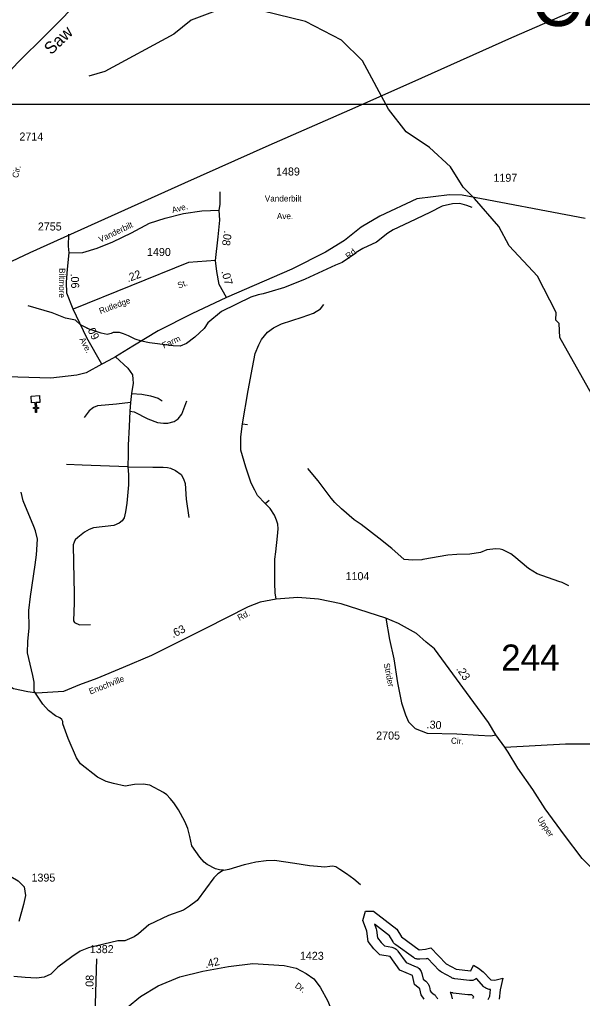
# Model space of a CAD drawing. Extents: x 1473865 to 1648260, y 639067 to 773536.
# Drawn here: x 1505359 to 1509749, y 649038 to 656681 of the extents above; entities that cross this region are included whole.
import ezdxf

# ---------------------------------------------------------------- set-up
doc = ezdxf.new("R2010")
doc.units = 0
for name, color, linetype in [('Exist Cultural Church CELL', 7, 'Continuous'), ('Exist Hydrographic Buffer Line', 7, 'Continuous'), ('Exist Hydrographic Creek Single Shore', 7, 'Continuous'), ('Exist Hydrographic Lake Shore', 7, 'Continuous'), ('Exist Hydrographic Misc Water Feature', 7, 'Continuous'), ('Exist Road Non-System Type 51', 7, 'Continuous'), ('Exist Road Non-System Type 51 Label', 7, 'Continuous'), ('Exist Road Secondary Mileage Hundredths English Label', 7, 'Continuous'), ('Exist Road Secondary Structure Culvert Number Label', 7, 'Continuous'), ('Exist Road Secondary Structure Standard Bridge Number Label', 7, 'Continuous'), ('Exist Road Secondary Type 51 Attributed', 7, 'Continuous'), ('Exist Road Secondary Type 51 Label', 7, 'Continuous'), ('Exist Road Secondary Type 51 Number Label', 7, 'Continuous'), ('Exist Utilities Electrical Transmission Line', 7, 'Continuous'), ('Map Preparation Inset Cut Line', 7, 'Continuous')]:
    doc.layers.add(name, color=color, linetype=linetype)

msp = doc.modelspace()

# ---------------------------------------------------------------- linework, layer by layer
at = {"layer": 'Exist Cultural Church CELL'}
msp.add_lwpolyline([(1505516.8, 653691.9), (1505488.4, 653690.4), (1505490.4, 653652.3), (1505506.3, 653653.2), (1505506.7, 653645.2), (1505490.8, 653644.4), (1505492.3, 653614.3), (1505484.3, 653613.9), (1505482.8, 653644), (1505466.8, 653643.1), (1505466.4, 653651.1), (1505482.3, 653651.9), (1505480.4, 653690), (1505451.6, 653688.5), (1505448.8, 653741.7), (1505514, 653745.1)], close=True, dxfattribs=at)
at = {"layer": 'Exist Hydrographic Buffer Line'}
for points in [[(1509013, 649028.5), (1509027.3, 649055), (1509033.2, 649107.1), (1509029, 649107.4), (1509021.8, 649108.2), (1509014.8, 649109.8), (1509007.9, 649111.9), (1509001.3, 649114.8), (1508995, 649118.3), (1508989, 649122.3), (1508983.4, 649126.9), (1508978.4, 649132.1), (1508925.4, 649190.9), (1508923.6, 649192.3), (1508915.6, 649186.9), (1508904.9, 649181.9), (1508893.5, 649178.6), (1508881.7, 649177.2), (1508869.9, 649177.7), (1508754.9, 649191.2), (1508747.7, 649192.4), (1508740.5, 649194.3), (1508733.7, 649196.9), (1508727.1, 649200.2), (1508650.4, 649243.1), (1508641.2, 649249.2), (1508633, 649256.5), (1508544.1, 649348.9), (1508543.9, 649348.8), (1508536.7, 649347.3), (1508529.5, 649346.5), (1508480.5, 649343.4), (1508474.1, 649343.3), (1508467.7, 649343.7), (1508461.3, 649344.7), (1508455.1, 649346.2), (1508449, 649348.2), (1508443.1, 649350.8), (1508437.4, 649353.8), (1508432.1, 649357.3), (1508293.3, 649456.9), (1508287.3, 649461.6), (1508281.9, 649467), (1508277, 649472.9), (1508272.7, 649479.2), (1508243.7, 649527.6), (1508128, 649618.3), (1508138.8, 649589.4), (1508141.5, 649580.5), (1508143.1, 649571.3), (1508149.8, 649511.2), (1508179, 649474.2), (1508204.7, 649448.5), (1508263.2, 649437.7), (1508270.2, 649436.1), (1508277, 649433.7), (1508283.6, 649430.8), (1508289.8, 649427.2), (1508295.7, 649423.1), (1508301.2, 649418.4), (1508306.1, 649413.2), (1508310.6, 649407.5), (1508373.7, 649319.2), (1508453.8, 649285.2), (1508461.8, 649281.2), (1508469.3, 649276.3), (1508476.2, 649270.5), (1508482.3, 649264), (1508487.6, 649256.8), (1508492, 649249), (1508495.4, 649240.7), (1508497.8, 649232.1), (1508507.2, 649189.1), (1508528.2, 649172.6), (1508533.3, 649168.2), (1508538, 649163.3), (1508542.2, 649158.1), (1508546, 649152.5), (1508549.2, 649146.6), (1508551.9, 649140.4), (1508554, 649134), (1508555.5, 649127.4), (1508561.5, 649095.8), (1508568.7, 649085.8), (1508592.3, 649068.7), (1508597.1, 649064.8), (1508601.6, 649060.6), (1508605.8, 649056.1), (1508609.5, 649051.2), (1508612.9, 649046), (1508615.8, 649040.5), (1508618.2, 649034.8)], [(1508897.3, 649036.9), (1508898.5, 649041.5), (1508900.3, 649047.7), (1508901.3, 649050.8), (1508898.8, 649053.3), (1508896.9, 649055.2), (1508895.1, 649057.2), (1508887.7, 649065.4), (1508886.3, 649065.3), (1508877.4, 649065.3), (1508865.6, 649065.7), (1508861.2, 649066), (1508856.8, 649066.4), (1508741.8, 649080), (1508739.1, 649080.3), (1508736.4, 649080.7), (1508729.1, 649082), (1508723.7, 649083), (1508718.9, 649084.2), (1508721.1, 649079.2), (1508722.8, 649074.9), (1508724.4, 649070.6), (1508726.4, 649064.7), (1508727.7, 649060.3), (1508728.9, 649055.9), (1508730.4, 649049.9), (1508731.4, 649045.4), (1508732.3, 649040.8), (1508733.2, 649034.7)]]:
    msp.add_lwpolyline(points, dxfattribs=at)
at = {"layer": 'Exist Hydrographic Creek Single Shore'}
for points in [[(1508908.8, 655285.2), (1508818.8, 655372.4), (1508720.8, 655531.9), (1508556.8, 655682.9), (1508375.8, 655804.7), (1508236.8, 655981.6), (1508034.8, 656359.8), (1507870.8, 656520.7), (1507589.8, 656667.5), (1507141.8, 656775), (1506966.8, 656778.5), (1506697.8, 656675.6), (1506562.8, 656566.7), (1506023.8, 656275.6), (1505898.8, 656238.8)], [(1510180, 652516.1), (1510180, 652579.4), (1510146.9, 652645.8), (1510074.5, 652778.5), (1510026.2, 652862.9), (1510065.4, 652935.3), (1510026.2, 653001.7), (1509993, 653101.2), (1509937.8, 653551), (1509573.8, 654198.4), (1509567.8, 654306.9), (1509542.8, 654333.7), (1509543.8, 654392.7), (1509398.7, 654677.9), (1509177.8, 654915.5), (1509096.8, 655064.8), (1508908.8, 655285.2)]]:
    msp.add_lwpolyline(points, dxfattribs=at)
at = {"layer": 'Exist Hydrographic Lake Shore'}
msp.add_lwpolyline([(1508515, 649032.2), (1508490.9, 649065.3), (1508481.8, 649113.6), (1508439.6, 649146.8), (1508424.5, 649216.2), (1508325, 649258.4), (1508249.6, 649364), (1508168.1, 649379), (1508122.9, 649424.3), (1508077.6, 649481.6), (1508068.6, 649563), (1508050.5, 649611.3), (1508035.4, 649647.5), (1508058.2, 649719.1), (1508119.9, 649719.9), (1508300.8, 649578.1), (1508337, 649517.8), (1508475.8, 649418.3), (1508524.8, 649421.3), (1508567.6, 649432.6), (1508687.1, 649308.5), (1508763.7, 649265.7), (1508878.6, 649252.1), (1508898.9, 649297.3), (1508939.7, 649274.4), (1508976.5, 649246.3), (1509034.1, 649182.2), (1509067, 649180), (1509129.7, 649195.1), (1509108.5, 649105.5), (1509100.2, 649032.2)], dxfattribs=at)
at = {"layer": 'Exist Hydrographic Misc Water Feature'}
for points in [[(1508890.4, 655213.1), (1508847.7, 655229.4), (1508792, 655244.4), (1508735.9, 655241.5), (1508655.6, 655225), (1508558.7, 655174.8), (1508400.5, 655099.4), (1508272.4, 655040.3), (1508231.9, 655013.1), (1508142.6, 654942.8), (1508037.8, 654894.8), (1507985.2, 654863.8), (1507981.1, 654857.9), (1507875.8, 654783.9), (1507823.4, 654762.9), (1507585.6, 654653.5), (1507426.2, 654590.1), (1507303.7, 654552.9), (1507259.5, 654539.7), (1507219.4, 654532.5), (1507163.1, 654513.5), (1506933.1, 654401.9), (1506827.5, 654313.6), (1506798.7, 654268.6), (1506725.5, 654202), (1506660.6, 654151.2), (1506612.3, 654132.1), (1506556.3, 654133.2), (1506516.4, 654137.9), (1506372.8, 654156.6), (1506309, 654169.8), (1506261.3, 654186.7), (1506209.8, 654211.6), (1506170.1, 654228.4), (1506138.3, 654237), (1506090.3, 654237.9), (1506074.1, 654230.2), (1506042, 654222.8), (1505994.2, 654231.7), (1505901.2, 654264.4), (1505835.4, 654298.6), (1505796.1, 654335.3), (1505718.4, 654348.8), (1505613.2, 654390.8), (1505426.2, 654446.2)], [(1509642.5, 652258.7), (1509633.9, 652264.5), (1509590.4, 652285.3), (1509566.5, 652293.7), (1509397.6, 652352.2), (1509328.3, 652394.2), (1509214.2, 652492.2), (1509190.4, 652508.7), (1509129, 652539.8), (1509107.2, 652546.2), (1509075.2, 652548.8), (1509003.1, 652540.2), (1508954.7, 652521.1), (1508870.4, 652506.7), (1508770.5, 652504.6), (1508698.4, 652497.9), (1508505.8, 652465.6), (1508497.7, 652461.7), (1508425.7, 652459.1), (1508357.8, 652464.3), (1508263.4, 652550.1), (1508160.8, 652632), (1508022.8, 652738.5), (1507967.8, 652776.1), (1507870.9, 652859.7), (1507818, 652910.2), (1507790.6, 652944.7), (1507687.1, 653080.6), (1507606.8, 653176)], [(1506949.7, 650038.7), (1506918.3, 650041), (1506886.4, 650049.6), (1506823.1, 650082.8), (1506799.4, 650101.2), (1506764.1, 650141.8), (1506701.7, 650228.9), (1506687, 650301.2), (1506672.2, 650365.4), (1506649.2, 650419.8), (1506598.9, 650510.7), (1506561.8, 650565.4), (1506534.5, 650597.9), (1506507, 650626.4), (1506481.4, 650646.8), (1506374.3, 650702.8), (1506323.9, 650709.7), (1506254.5, 650709.1), (1506182.3, 650694.4), (1506090.6, 650716.1), (1506035, 650731.1), (1505967.6, 650766.4), (1505833.5, 650868.8), (1505802.3, 650917.4), (1505737, 651066.6), (1505695.2, 651183.2), (1505695.5, 651199.2), (1505687.8, 651215.4), (1505672, 651229.7), (1505640.3, 651244.2), (1505585.1, 651285.2), (1505540, 651336.1), (1505473.3, 651435.9), (1505473.1, 651507.2), (1505462, 651559.4), (1505421.2, 651736.1), (1505422.8, 651824), (1505432.7, 651931.7), (1505431.2, 652067.7), (1505445.1, 652175.3), (1505481.6, 652422.5), (1505491.1, 652502.2), (1505498.4, 652623.9), (1505482.5, 652690.3), (1505471.1, 652722.5), (1505386.7, 652923.9), (1505371.9, 652992.2)], [(1506949.7, 650038.7), (1506994.4, 650047.6), (1507113, 650083.3), (1507201.4, 650105.6), (1507283.6, 650116.1), (1507347.6, 650116.9), (1507507.1, 650093.9)], [(1507507.1, 650093.9), (1507621.3, 650076.2), (1507683.4, 650069.7), (1507740.2, 650065.9), (1507779.1, 650070.3), (1507799.8, 650072.4), (1507825.6, 650066.7), (1507856.2, 650047.9), (1507910, 650013.2), (1507966, 649970.6), (1508018.3, 649928.1)], [(1506949.7, 650038.7), (1506905.7, 650011.3), (1506873.2, 649979.9), (1506744, 649802.4), (1506685.2, 649757.6), (1506636.7, 649726.5), (1506519.9, 649684.7), (1506366.6, 649611.6), (1506285.4, 649541.2), (1506252.9, 649517.9), (1506180.4, 649487.2), (1506124.5, 649488.3), (1505895.5, 649432.6), (1505831, 649405.8), (1505766.2, 649363.1), (1505656.8, 649281.2), (1505603.8, 649226.2), (1505551.5, 649203.3), (1505491.3, 649196.4), (1505403.4, 649200), (1505315.5, 649209.7)]]:
    msp.add_lwpolyline(points, dxfattribs=at)
at = {"layer": 'Exist Road Non-System Type 51'}
for p, q in [((1506233.1, 653762.6), (1506224.8, 653692.4)), ((1506224.8, 653692.4), (1506218, 653624.6)), ((1507098.8, 653525.8), (1507137.3, 653519.8)), ((1507274.5, 652903.7), (1507305.4, 652928.5))]:
    msp.add_line(p, q, dxfattribs=at)
for points in [[(1505746.1, 654859), (1505853.6, 654863.7), (1505963.1, 654895.4), (1506087.5, 654946), (1506233.3, 655015), (1506372.9, 655091.2), (1506495.5, 655129.5), (1506638.3, 655167.8), (1506781.8, 655186.8), (1506916, 655193.4)], [(1505746.1, 654859), (1505741.7, 654911), (1505742, 655004.6)], [(1505733.5, 654733.2), (1505746.1, 654859)], [(1507098.8, 653525.8), (1507143.3, 653783.7), (1507176.5, 653965.4), (1507196.9, 654073.3), (1507225.5, 654141.9), (1507247.4, 654183.4), (1507293.4, 654239.2), (1507340.9, 654274.6), (1507401.2, 654305.5), (1507563.3, 654357.6), (1507651.6, 654389.2), (1507707.4, 654423.9), (1507732.3, 654455.6)], [(1506107.6, 654047.6), (1506203.7, 653958.6), (1506239.9, 653907.4), (1506242.9, 653874.2), (1506245.2, 653843.3), (1506233.1, 653762.6)], [(1506233.1, 653762.6), (1506313.8, 653757.3), (1506380.2, 653742.2), (1506440.5, 653724.1), (1506471.4, 653703)], [(1506224.8, 653692.4), (1506114.7, 653678.1), (1505966.9, 653664.5), (1505936, 653653.2), (1505900.6, 653626.1), (1505863.6, 653573.3)], [(1506218, 653624.6), (1506253.5, 653617.8), (1506360.6, 653564.2), (1506433.7, 653534.8), (1506481.2, 653528.8), (1506514.4, 653528.8), (1506564.2, 653541.6), (1506595.1, 653563.5), (1506626, 653598.9), (1506663.7, 653704.5)], [(1506218, 653624.6), (1506214.3, 653503.9), (1506205.2, 653356.9), (1506205.2, 653286.7), (1506203.7, 653188.7)], [(1507274.5, 652903.7), (1507214.2, 652966.3), (1507193.8, 653005.5), (1507164.4, 653062), (1507123, 653185.7), (1507086, 653319.2), (1507083.7, 653362.9), (1507083.7, 653422.5), (1507098.8, 653525.8)], [(1506203.7, 653188.7), (1505846.3, 653202.3), (1505724.1, 653206.8)], [(1506203.7, 653188.7), (1506209.8, 653129.1), (1506209.8, 653049.2), (1506196.9, 652905.9), (1506184.9, 652837.3), (1506173.6, 652789.8), (1506160, 652767.2), (1506135.1, 652748.3), (1506095.1, 652729.5), (1505936.8, 652712.1), (1505901.3, 652700.8), (1505864.4, 652678.9), (1505812.3, 652637.5), (1505792, 652618.6), (1505783.7, 652599.8), (1505776.9, 652579.4), (1505779.2, 652442.2), (1505785.2, 652197.1), (1505785.2, 652126.9), (1505779.9, 651985.9), (1505787.5, 651973.9), (1505825.9, 651955), (1505911.9, 651956.5)], [(1506203.7, 653188.7), (1506399, 653187.2), (1506478.2, 653187.2), (1506513.7, 653182.7), (1506536.3, 653177.4), (1506574.7, 653160.8), (1506618.5, 653129.9), (1506638.8, 653094.4), (1506650.9, 653059), (1506659.2, 652936.8), (1506678.8, 652792.1)], [(1507359.7, 652156.4), (1507352.2, 652206.1), (1507349.9, 652280), (1507351.4, 652404.5), (1507351.4, 652467), (1507359, 652525.1), (1507371.1, 652647.3), (1507376.3, 652705.3), (1507372.6, 652740), (1507364.3, 652773.2), (1507347.7, 652810.9), (1507314.5, 652862.2), (1507274.5, 652903.7)], [(1509143.5, 650999.1), (1509616.5, 651025.3), (1510035.8, 651025.3), (1510345.2, 651016.6)]]:
    msp.add_lwpolyline(points, dxfattribs=at)
at = {"layer": 'Exist Road Secondary Type 51 Attributed'}
for points in [[(1505158.5, 656145.5), (1505346.5, 656347.2), (1505567.3, 656564.8), (1505873.4, 656877.7), (1506053.7, 657064), (1506308.5, 657324.9), (1506447.3, 657478), (1506532.1, 657592.5), (1506701.7, 657864.1), (1506751.5, 657960.8), (1506777.9, 658039.9)], [(1506887, 654799.4), (1506909.1, 654983.6), (1506920.2, 655116.3), (1506916, 655193.4), (1506923.8, 655237.9), (1506923.8, 655337.4)], [(1509771.7, 655126.8), (1508811.6, 655310.6), (1508711.9, 655313.8), (1508457.7, 655280.4), (1508170.3, 655145.7), (1508022.4, 655059.2), (1507892.9, 654955.4), (1507745.4, 654865.7), (1507482.7, 654733), (1506973.3, 654511.3)], [(1506887, 654799.4), (1506677.1, 654784.6), (1505777.6, 654419.8)], [(1506973.3, 654511.3), (1506917.1, 654612.4), (1506897.9, 654714.1), (1506887, 654799.4)], [(1505777.6, 654419.8), (1505726.6, 654545.8), (1505723.9, 654631.8), (1505733.5, 654733.2)], [(1506973.3, 654511.3), (1506703, 654383.8), (1506439.9, 654250.3), (1506243, 654131.5), (1506107.6, 654047.6), (1506054.5, 654019.6), (1506000.3, 653989.8)], [(1506000.3, 653989.8), (1505884.9, 654196.6), (1505777.6, 654419.8)], [(1506000.3, 653989.8), (1505877.2, 653922.8), (1505804.8, 653903.4), (1505603.6, 653881.8), (1504996.5, 653898.9), (1504811.6, 653896.1), (1504735.8, 653888.7), (1504655.4, 653871.1), (1504576.9, 653837.8), (1504492.8, 653807.3)], [(1508215.5, 652006.8), (1507866.8, 652118.1), (1507691.5, 652154.8), (1507529.7, 652169.5), (1507359.7, 652156.4), (1507236.8, 652131.5), (1507141.8, 652095.3), (1506808.2, 651926.6), (1506387.7, 651716), (1506168.1, 651621.8), (1505962.9, 651536.8), (1505826.2, 651486.9), (1505702.2, 651435.7), (1505576.5, 651426.1), (1505493.3, 651422.4), (1505423.4, 651431.6), (1505312.8, 651456.3), (1505173.1, 651544.8)], [(1509075.3, 651097.1), (1509016.5, 651192.2), (1508595.9, 651766.7), (1508531.1, 651820.8), (1508455.4, 651887.8), (1508314.9, 651965.7), (1508215.5, 652006.8)], [(1508215.5, 652006.8), (1508244.6, 651840.3), (1508278.2, 651689.8), (1508307.2, 651503.3), (1508337.4, 651347.2), (1508368.2, 651251.7)], [(1508368.2, 651251.7), (1508392.6, 651196.5), (1508444.5, 651146.7), (1508539.6, 651109.9), (1508768.7, 651103.4), (1508937.8, 651093.3), (1509034.8, 651087.8), (1509075.3, 651097.1)], [(1510974.3, 649458.1), (1510706, 649547.5), (1510476.6, 649621.9), (1510372.4, 649661.8), (1510170.8, 649767), (1510037.4, 649858.5), (1509866.7, 650010.4), (1509748.5, 650130.4), (1509609.7, 650312.2), (1509458.8, 650518.6), (1509362.3, 650669.1), (1509246.6, 650834.9), (1509170.9, 650961.6), (1509143.5, 650999.1), (1509075.3, 651097.1)], [(1505032.6, 650151), (1505290.8, 649989.3), (1505347.8, 649955.1), (1505364.9, 649940.8), (1505395.9, 649910.5), (1505404.4, 649842), (1505390.2, 649770.6), (1505353.1, 649639.4)], [(1505951.5, 648924.6), (1505950.5, 648994.7), (1505962.2, 649346.8)], [(1506137.7, 648941.7), (1506202.1, 648970.8), (1506303.4, 649053.2), (1506440.8, 649135.1), (1506609.9, 649206.3), (1506788.4, 649249.5), (1506989.1, 649288.3), (1507177.4, 649309.3), (1507423.1, 649295.6), (1507516.9, 649274.1), (1507594.1, 649232.9), (1507655.5, 649189.8), (1507704.6, 649125), (1507764.8, 649016.1), (1507807, 648905.4), (1507841.2, 648786.9), (1507867.6, 648678.5)]]:
    msp.add_lwpolyline(points, dxfattribs=at)
at = {"layer": 'Exist Utilities Electrical Transmission Line'}
msp.add_lwpolyline([(1509710.8, 656762.3), (1509197, 656538.7), (1508494, 656224.3), (1507974.2, 655991.1), (1507303.4, 655698.1), (1506646.5, 655403), (1505969.6, 655098.2), (1505439.7, 654859), (1504964, 654634.9), (1504530.8, 654436.1), (1504168, 654270.1), (1503557.6, 653996.3), (1503342.2, 653899.8), (1503190.9, 653832.2), (1502578.4, 653670.4)], dxfattribs=at)
at = {"layer": 'Map Preparation Inset Cut Line'}
msp.add_lwpolyline([(1500603.9, 656021.6), (1510544.7, 656021.6), (1510544.7, 642848.3), (1500603.9, 642848.3)], close=True, dxfattribs=at)

# ---------------------------------------------------------------- texts
at = {"layer": 'Exist Road Non-System Type 51 Label'}
for s, rotation, p in [('Ave.', 15.00826, (1506553.3, 655169.8)), ('Vanderbilt', 25.33225, (1505989.2, 654940))]:
    msp.add_text(s, height=47.5, rotation=rotation, dxfattribs=at).set_placement(p)
at = {"layer": 'Exist Road Secondary Mileage Hundredths English Label'}
for s, rotation, p in [('.08', 261.44959, (1506955, 655035.1)), ('.06', 271.78832, (1505758.3, 654697.2)), ('.22', 20.51291, (1506204.9, 654629.3)), ('.07', 284.9241, (1506933, 654714.8)), ('.09', 295.69002, (1505878, 654277.8)), ('.63', 27.18828, (1506556.5, 651850.2)), ('.23', 304.15421, (1508762.5, 651610)), ('.30', 355.93695, (1508532.3, 651147.7)), ('.42', 13.60816, (1506810.9, 649273.1)), ('.08', 88.09026, (1505934.4, 649104.6))]:
    msp.add_text(s, height=62.5, rotation=rotation, dxfattribs=at).set_placement(p)
at = {"layer": 'Exist Road Secondary Structure Culvert Number Label'}
msp.add_text('C241', height=410.1, dxfattribs=at).set_placement((1509349.8, 656631.3))
at = {"layer": 'Exist Road Secondary Structure Standard Bridge Number Label'}
msp.add_text('244', height=205.05, dxfattribs=at).set_placement((1509115.2, 651596.4))
at = {"layer": 'Exist Road Secondary Type 51 Label'}
for s, height, rotation, p in [('Saw', 95, 43.90202, (1505605, 656400.9)), ('Cir.', 47.5, 76.28336, (1505346.2, 655440.9)), ('Rd.', 47.5, 38.71268, (1507924.9, 654809)), ('Biltmore', 47.5, 269.52908, (1505668.2, 654740.9)), ('St.', 47.5, 20.51291, (1506601.5, 654580.4)), ('Rutledge', 47.5, 20.51291, (1505990.1, 654381)), ('Ave.', 47.5, 297.96948, (1505824.1, 654184.7)), ('Farm', 47.5, 25.09372, (1506484.9, 654112.1)), ('Rd.', 47.5, 27.18828, (1507073.3, 651986.1)), ('Strider', 47.5, 281.97115, (1508197.8, 651650.6)), ('Enochville', 47.5, 21.46496, (1505911.2, 651410.5)), ('Cir.', 47.5, 355.93683, (1508722.6, 651028.1)), ('Upper', 47.5, 303.43216, (1509395.4, 650437.1)), ('Dr.', 47.5, 324.94244, (1507502.6, 649127))]:
    msp.add_text(s, height=height, rotation=rotation, dxfattribs=at).set_placement(p)
for s, p in [('Vanderbilt', (1507271.8, 655260.7)), ('Ave.', (1507366.3, 655123))]:
    msp.add_text(s, height=47.5, dxfattribs=at).set_placement(p)
at = {"layer": 'Exist Road Secondary Type 51 Number Label'}
for s, p in [('2714', (1505357.7, 655736.8)), ('1489', (1507359.5, 655463.7)), ('1197', (1509055.4, 655414.7)), ('2755', (1505501.5, 655034.4)), ('1490', (1506353, 654835.4)), ('1104', (1507901.6, 652303.9)), ('2705', (1508140.7, 651059.2)), ('1395', (1505452, 649950)), ('1382', (1505906.8, 649391.5)), ('1423', (1507545.8, 649339.2))]:
    msp.add_text(s, height=62.5, dxfattribs=at).set_placement(p)

doc.saveas('drawing.dxf')
